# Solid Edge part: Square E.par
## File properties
Title: Square 47 x 47 Cm
Author: DESYS
Template: Normal.par
Last saved by: Administrator
Revision: 6
Application: Solid Edge
Tipo di contenuto documento: 0
Precisione: 0,990
Document Number: 8007/E
Revision: 0
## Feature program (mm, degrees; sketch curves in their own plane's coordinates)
sketch for "unnamed Protrusion 1" plane through (0, 0, 0) normal (0, 0, 1) x-axis (1, 0, 0)
  line (0, 0) -> (0, -475)
  line (0, 0) -> (475, 0)
extrude "unnamed Protrusion 1" add finite 140 along -normal
sketch for "ExtrudedCutout_1" plane through (237.5, -237.5, 0) normal (0, 0, 1) x-axis (1, 0, 0)
  line (-197.5, 72.2729) -> (-197.5, -215.7383)
  line (-72.2729, 197.5) -> (215.7383, 197.5)
extrude "ExtrudedCutout_1" cut finite 110 along -normal
fillet "Rotondo_1" radius 100
fillet "Rotondo_2" radius 20
fillet "Rotondo_3" radius 20
sketch for "ExtrudedCutout_2" plane through (237.5, -237.5, -140) normal (0, 0, -1) x-axis (1, 0, 0)
  line (-217.5, -88.8393) -> (-217.5, -217.5)
  line (-88.8393, -217.5) -> (-217.5, -217.5)
extrude "ExtrudedCutout_2" cut finite 125 along -normal
sketch for "ExtrudedCutout_3" plane through (237.5, -237.5, -140) normal (0, 0, -1) x-axis (1, 0, 0)
  line (-217.5, -88.8393) -> (-217.5, 207.0503)
  line (-88.8393, -217.5) -> (207.0503, -217.5)
  arc centre (-237.5, -237.5) radius 150 from (-88.8393, -217.5) to (-217.5, -88.8393) ccw
extrude "ExtrudedCutout_3" cut finite 20 along -normal
sketch for "ExtrudedCutout_4" #1 plane through (232.2752, -232.2752, -120) normal (0, 0, -1) x-axis (1, 0, 0)
  line (-83.6145, -212.2752) -> (212.2752, -212.2752)
  arc centre (-232.2752, -232.2752) radius 445 from (210.9234, -192.2752) to (212.2752, -212.2752) cw
  line (210.9234, -192.2752) -> (-85.3058, -202.2752)
  arc centre (-232.2752, -232.2752) radius 150 from (-83.6145, -212.2752) to (-85.3058, -202.2752) ccw
sketch for "ExtrudedCutout_4" #2 plane through (232.2752, -232.2752, -120) normal (0, 0, -1) x-axis (1, 0, 0)
  line (-212.2752, -83.6145) -> (-212.2752, 212.2752)
  arc centre (-232.2752, -232.2752) radius 445 from (-212.2752, 212.2752) to (-192.2752, 210.9234) cw
  line (-192.2752, 210.9234) -> (-202.2752, -85.3058)
  arc centre (-232.2752, -232.2752) radius 150 from (-202.2752, -85.3058) to (-212.2752, -83.6145) ccw
  dimension (linear) = 212.2752
extrude "ExtrudedCutout_4" cut finite 90 along -normal
fillet "Rotondo_4" radius 110
fillet "Rotondo_5" radius 5  Radii2 = 10 mm
draft "Draft_1"  Angles1 = 5 deg
fillet "Rotondo_6" radius 5
fillet "Rotondo_7" radius 6
sketch for "Foro_2" plane through (237.4808, -237.4808, 0) normal (0, 0, 1) x-axis (-1, 0, 0)
  hole centre (165.4808, -165.4808) bore radius 17.5
  dimension (linear) = 165.4808
hole "Foro_2" diameter 35 through
sketch for "ExtrudedProtrusion_2" plane through (237.4808, -237.4808, -160) normal (0, 0, -1) x-axis (1, 0, 0)
  circle centre (-47.4808, -47.4808) radius 35
extrude "ExtrudedProtrusion_2" add  Profile_Plane1_Distance = 20 mm
sketch for "Foro_3" plane through (190, -190, -160) normal (0, 0, -1) x-axis (1, 0, 0)
  hole centre (0, 0) bore radius 25
hole "Foro_3" diameter 50 through
sketch for "ExtrudedProtrusion_3" plane through (0, 0, 0) normal (-0.707107, -0.707107, 0) x-axis (0, 0, 1)
  line (-153.8641, -233.7006) -> (-139.7567, -146.3303)
  arc centre (-120.0124, -149.5183) radius 20 from (-139.7567, -146.3303) to (-120.8259, -129.5349) cw
  line (-120.8259, -129.5349) -> (-15, -125.227)
extrude "ExtrudedProtrusion_3" add finite 50 symmetric
fillet "Rotondo_8" radius 10
fillet "Rotondo_9" radius 5
fillet "Rotondo_10" radius 5
fillet "Rotondo_11" radius 10
fillet "Rotondo_12" radius 10  Radii2 = 3 mm
sketch for "Foro_5" plane through (6.0768, -474.9611, -6) normal (0.707107, -0.707107, 0) x-axis (0, 0, -1)
  hole centre (19, 331.5513) bore radius 10
hole "Foro_5" diameter 20 to key point
sketch for "unnamed Cutout 1" #1 plane through (237.4808, 0, -70) normal (0, 1, 0) x-axis (1, 0, 0)
  line (-142.4808, 15) -> (-142.4808, 25)
  line (-162.4808, 25) -> (-162.4808, 15)
sketch for "unnamed Cutout 1" #2 plane through (237.4808, 0, -70) normal (0, 1, 0) x-axis (1, 0, 0)
  line (147.4808, 5) -> (157.4808, 5)
  line (157.4808, 25) -> (147.4808, 25)
extrude "unnamed Cutout 1" cut through along -normal
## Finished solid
Body 1: solid body, 145 faces, 315 edges, 172 vertices.
  Faces by surface: cylinder 52, blend 34, plane 23, torus 23, sphere 12, cone 1
  Edges by curve: circle 141, line 94, intersection 48, ellipse 32
Bounding box of the edges (mm; curved faces can reach further): 474.962 x 474.962 x 160.000, from (0, -474.9616, -160) to (474.9616, 0, 0).
Cylindrical faces by radius (mm): R5 x8, R6 x11, R10 x16, R17.5 x1, R20 x5, R25 x1, R35 x1, R100 x2, R110 x2, R150 x2, R170 x1, R455 x1, R475 x1
Conical faces (half-angle, radius in mm at the cone's reference point): 5 deg R445 x1
Toroidal faces (ring radius, tube radius in mm): R5 r5 x2, R15 r5 x2, R20.5 r3 x1, R26 r6 x4, R30 r5 x1, R35 r10 x1, R45 r10 x1, R145 r5 x2, R164 r6 x1, R430.7946 r5 x2, R435 r20 x1, R438.6686 r5 x1, R450.498 r6 x1, R461 r6 x1, R469 r6 x2
Spherical faces by radius (mm): R5 x5, R6 x6, R10 x1
Planar faces by outward normal: +x 2, +y 1, +z 3, -x 2, -y 1, -z 7, oblique 7
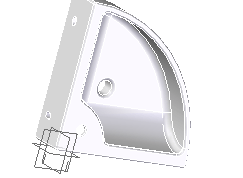
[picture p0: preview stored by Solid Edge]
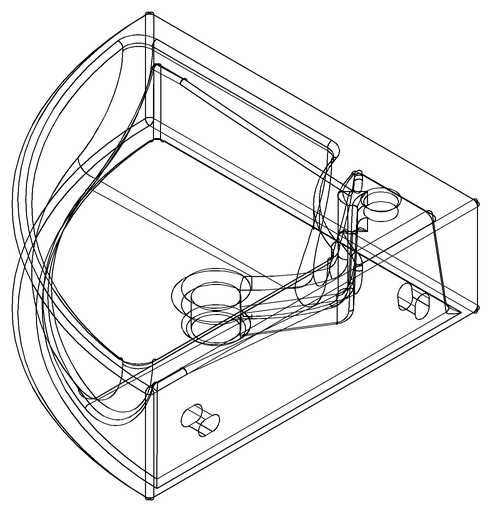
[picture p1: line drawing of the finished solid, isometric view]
